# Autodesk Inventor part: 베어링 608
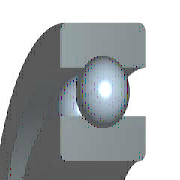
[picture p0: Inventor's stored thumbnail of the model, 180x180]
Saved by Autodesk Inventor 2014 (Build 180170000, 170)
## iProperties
IsCustomPart: 1
Created: 2012-02
Part Number: 베어링 608
Material: 강철, 연강
Description: 깊은 그루브 볼 베어링
Document SubType Name: Modeling
Standard: KS B 2023
Designer: mduedu
Standards Organization: KS
Language: ko-KR
Size Designation: 608 - 8 x 22 x 7
Categories: <MemberInstance><Categories><Category DisplayName="샤프트 부품" InternalName="7f7aeb1f-a693-4053-b835-cee3144e0d98" Mnemonic="SHFT"><Category DisplayName="베어링" Inter
Density: 7.86 g/cm^3
Mass: 12.1605 g
Surface Area: 20.0754 cm^2
Volume: 1.54714 cm^3
Appearance: 주황색
Author: mduedu
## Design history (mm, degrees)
sketch "스케치" dims "d0" = 3.64 (= -0.26 x WD + 0.26 x BD)
  geometry: L1 (1.68, 7.5)-(5.32, 7.5); L2 (3.5, 7.5)-(3.5, 5.68); L3 (3.5, 7.5)-(3.5, 9.32); L4 (2.148, 6.282)-(0, 6.282); L5 (0, 4)-(7, 4); L6 (2.148, 8.718)-(0, 8.718); L7 (0, 11)-(7, 11); L8 (7, 4)-(7, 6.282); L9 (4.852, 6.282)-(7, 6.282); L10 (4.852, 8.718)-(7, 8.718); L11 (7, 11)-(7, 8.718); L12 (-1.4, 0)-(8.4, 0) reference; L13 (0, -0.3)-(0, 5.3) reference
  constraints: 22 end point, 4 point on line, 2 collinear, 2 perpendicular, 2 symmetric about line, 1 midpoint, 1 parallel, 14 other
  dimensions: "d9" = 8 diameter of L5 L12 (= WD); "d11" = 22 diameter of L7 L12 (= BD); "d12" = 7 distance between parallel lines of L8 L13 (= KB); "d13" = 12.564 diameter of L9 L12 (= 0.326 x BD + 0.674 x WD)
revolve "본체" stored, may be unused: angle "d6" = 90 deg
revolve "볼" stored, may be unused: angle "d7" = 90 deg
pattern_circular "IDS_ARRAYBALL[SIMPL:T]" dims angle "d3" = 360 deg
body "Solid1"
fillet "모깎기1" dims "d1" = 0.3 (= KRS)
other parameters: "WD" = 8 [user parameter; used in 5 equation terms], "BD" = 22 [user parameter; used in 5 equation terms], "KB" = 7 [user parameter; used in 1 equation term], "KRS" = 0.3 [user parameter; used in 1 equation term], "d4" = 0, "d5" = 0, "d8" = 0, "d14" = 0, "d15" = 0, "BBA" = 0 [user parameter], "BC0" = 1370000 [user parameter], "BC" = 3250000 [user parameter], "BR" = 11 (= 0.5 x BD) [user parameter], "WR" = 4 (= 0.5 x WD) [user parameter]
